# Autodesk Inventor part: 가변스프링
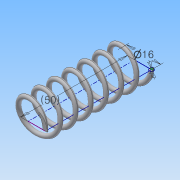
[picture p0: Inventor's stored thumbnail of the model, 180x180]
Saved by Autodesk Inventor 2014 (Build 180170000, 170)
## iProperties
Created: 2018-11
Part Number: 가변스프링
Material: Generic
Document SubType Name: Modeling
Designer: 703
Density: 1 g/cm^3
Appearance: Default
Author: 703
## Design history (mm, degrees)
sketch "스케치1"
  geometry: L1 (0, 0)-(-8, 0); L2 (-8, 0)-(-8, -43.5); L3 (-8, -43.5)-(0, -43.5); L4 (0, -43.5)-(0, 0); C1 r 1 at (0, 0); 1 further point
  constraints: 8 end point, 2 parallel, 1 centre point, 1 coincident, 1 horizontal, 1 perpendicular
  dimensions: "d0" = 2 diameter of C1; "d1" = 43.5 distance of L1.end L2.end (derived); "d2" = 16 diameter of point (0, 0) L2
feature "코일1" pitch "d3" = 10; turns "d5" = 7; dims "d4" = 43.5 (= d1), "d6" = 0, angle "d7" = 90 deg, angle "d8" = 90 deg, "d9" = 0, "d10" = 0
sketch "스케치2"
  geometry: C1 r 25 at (0, 0); 1 further point
  constraints: 1 centre point, 1 coincident
  dimensions: "d11" = 50 diameter of C1
extrude "돌출1" cut sketch "스케치2" distance "d12" = 10; taper "d13" = 0 deg
node "작업 평면1"
sketch "스케치3"
  geometry: C1 r 25 at (8, 0); 1 further point
  constraints: 1 centre point, 1 coincident
  dimensions: "d14" = 50 diameter of C1
extrude "돌출2" cut sketch "스케치3" distance "d15" = 10; taper "d16" = 0 deg
node "솔리드1"
